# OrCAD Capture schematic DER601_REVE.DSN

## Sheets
1 PAGE1: size C
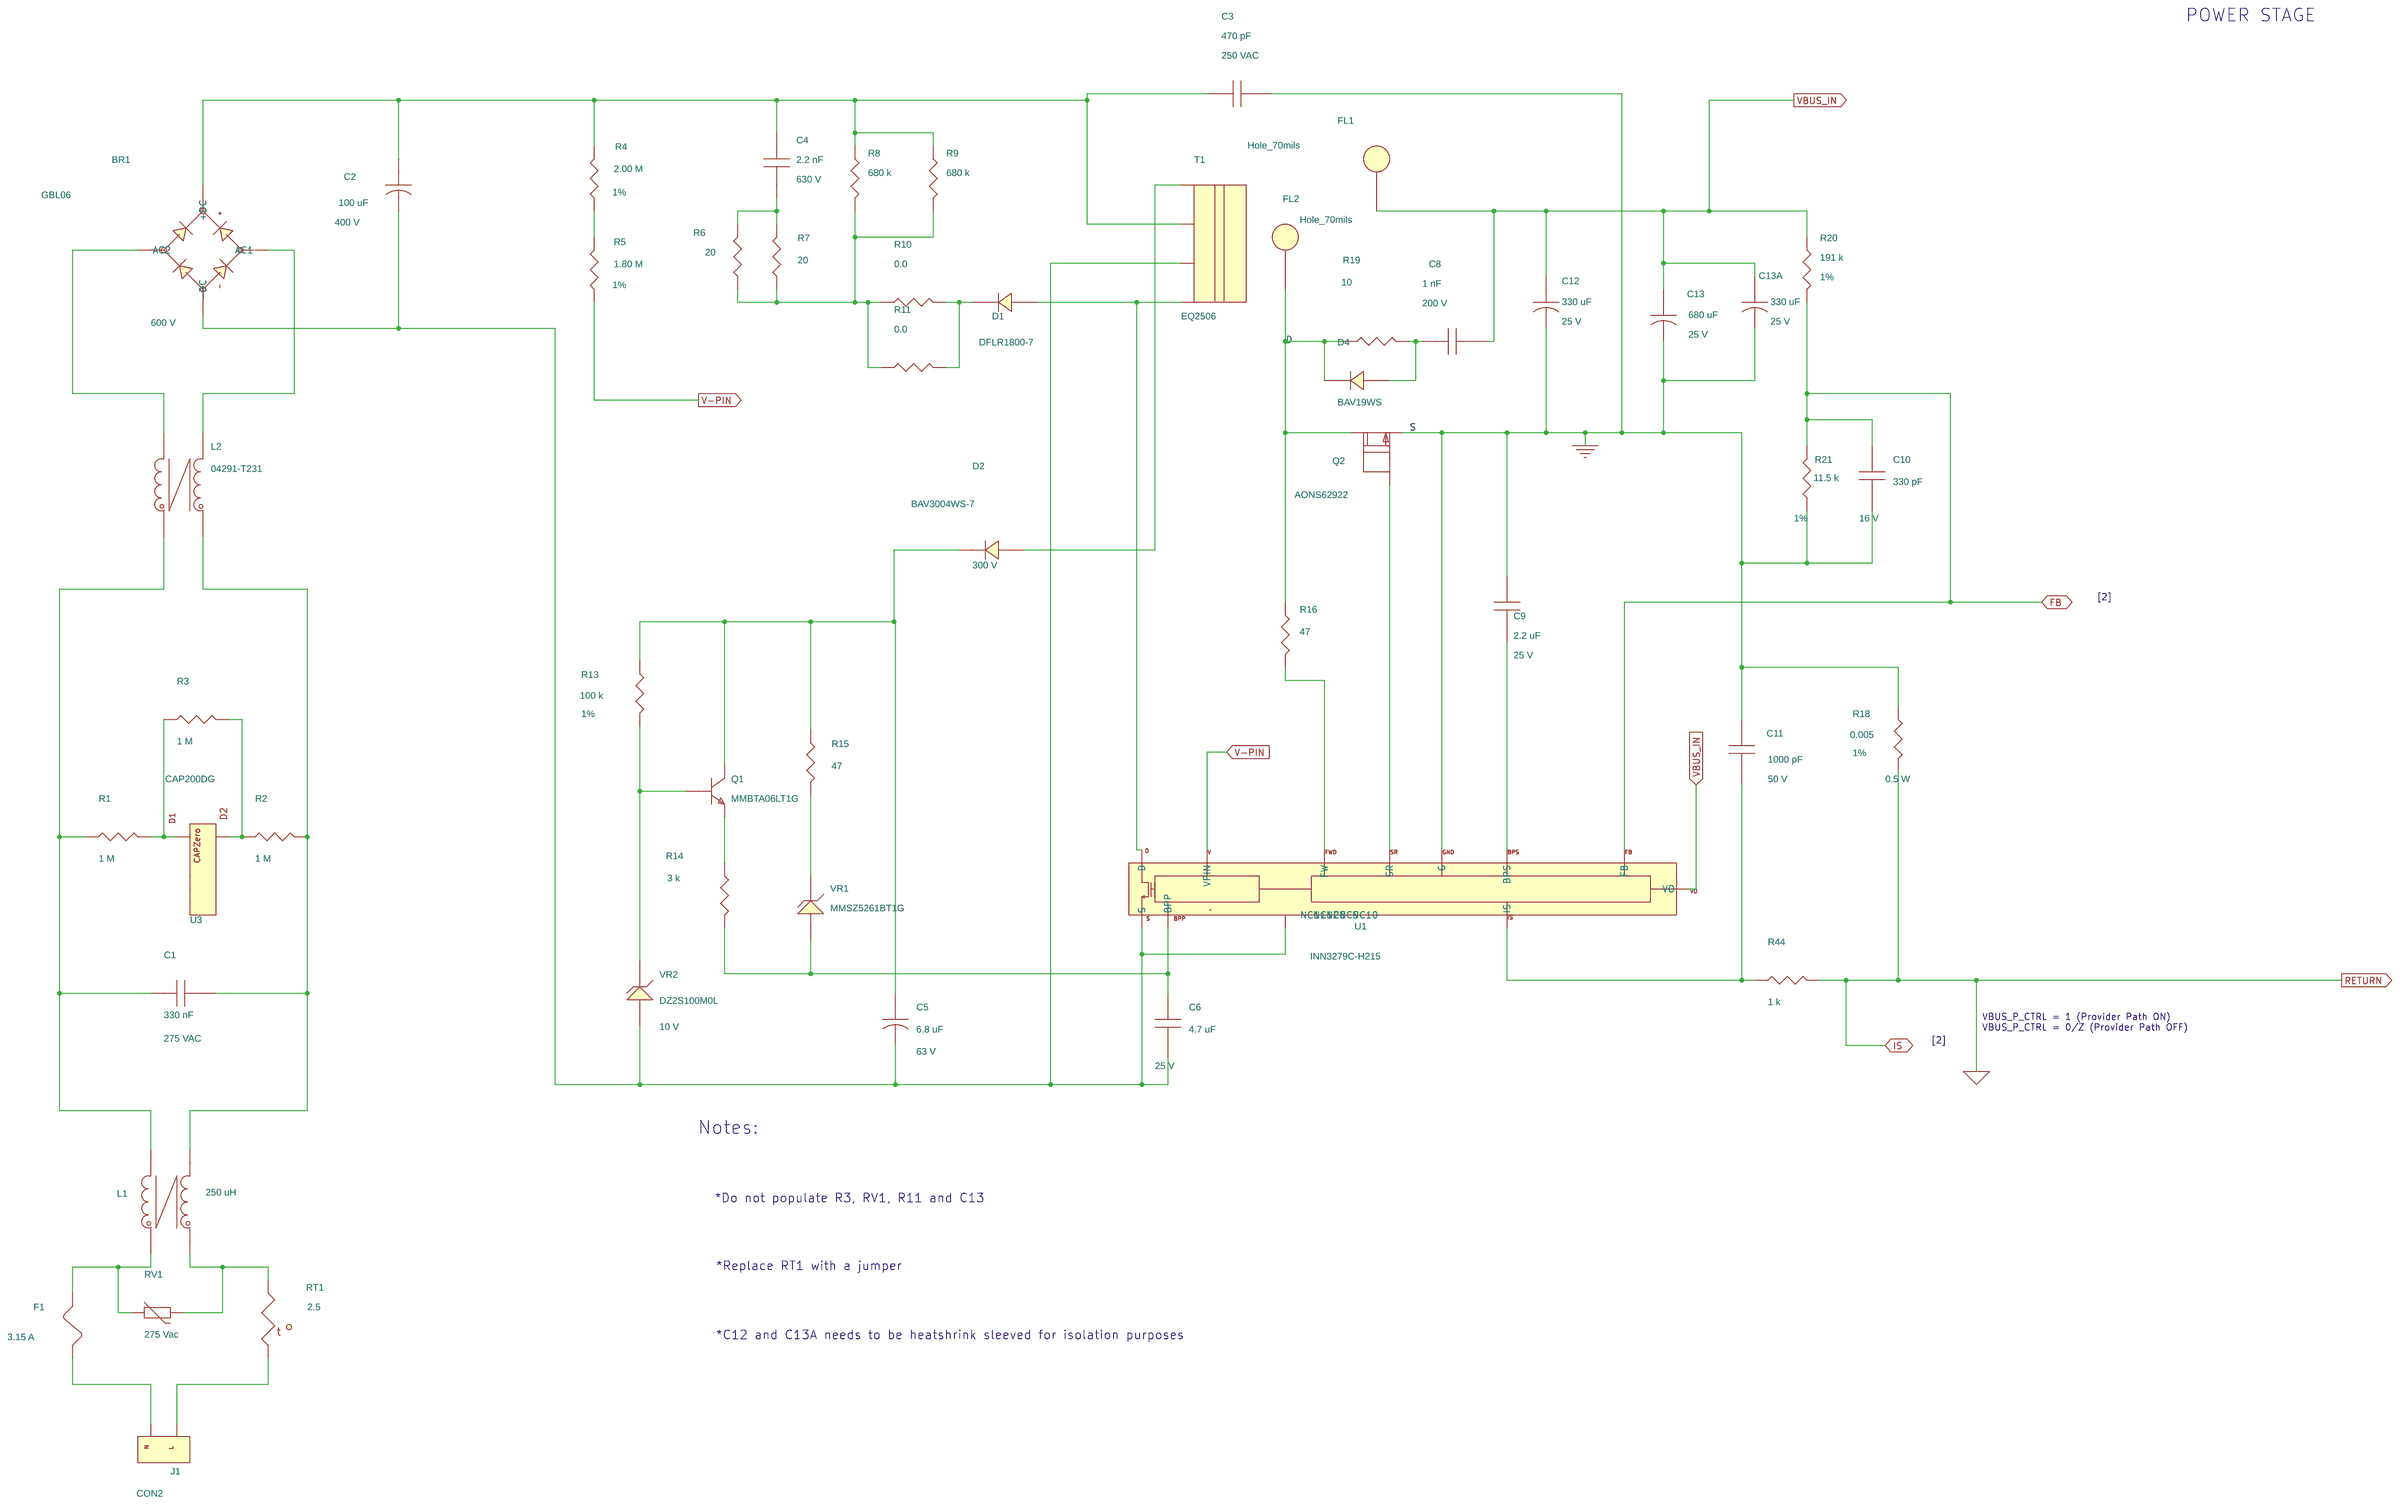
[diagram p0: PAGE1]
2 PAGE2: size Custom
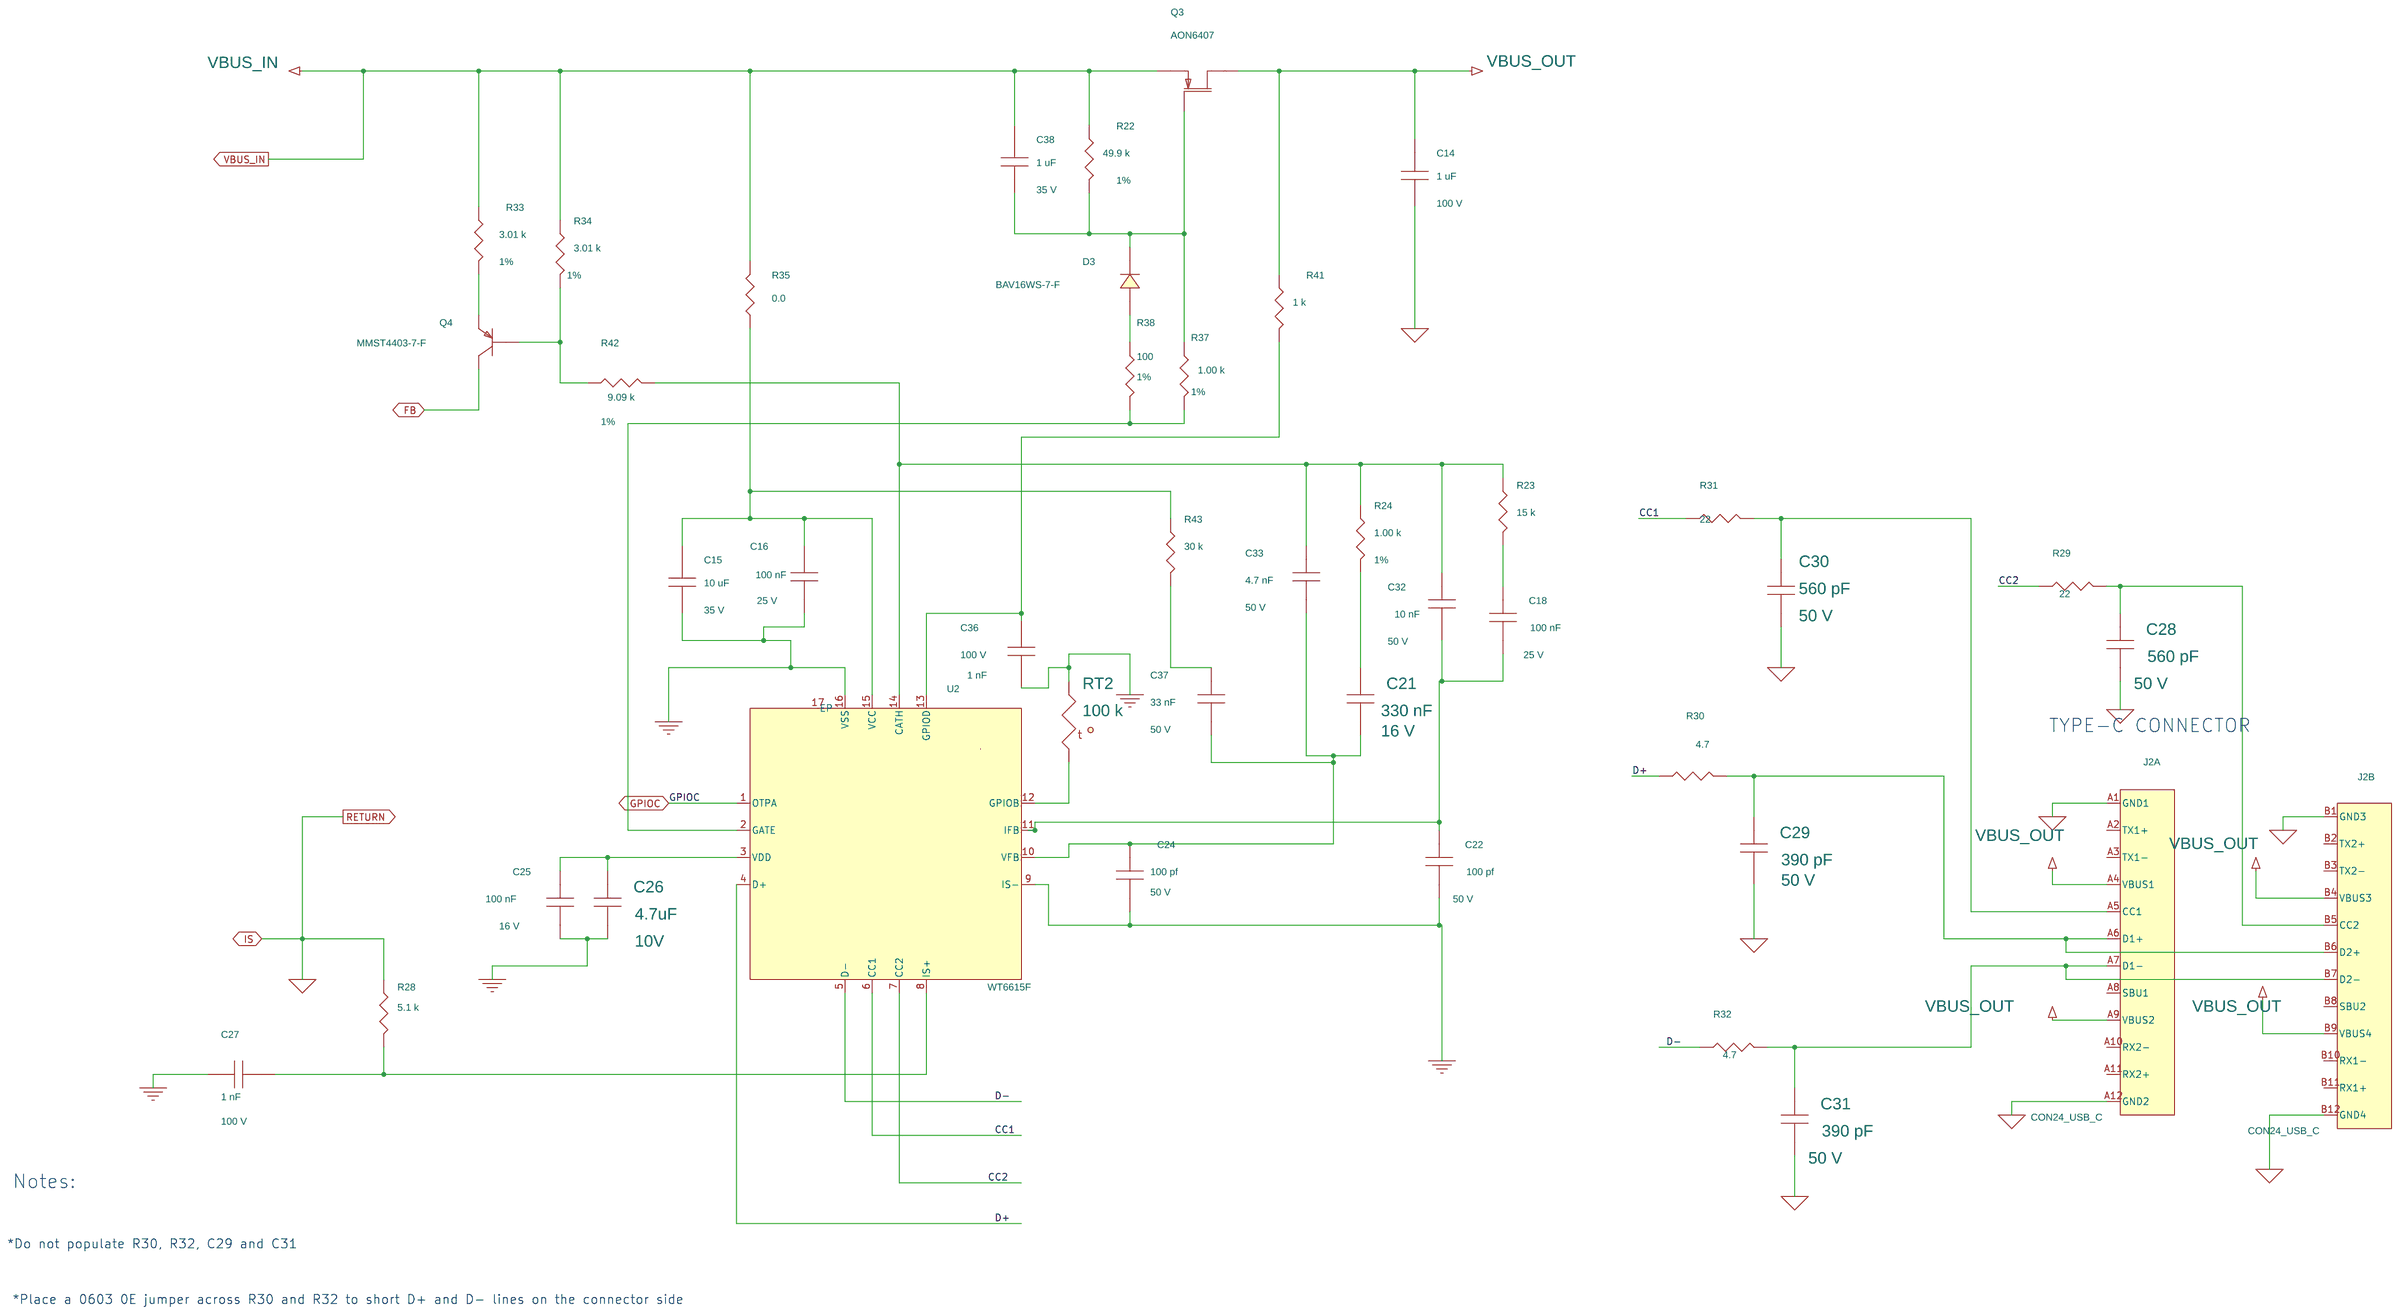
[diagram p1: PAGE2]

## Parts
sheet PAGE1
BR1  GBL06  [pidaxbridgegbl06]
C1  330 nF  [pinp_xcaprad15x8p5x14Hd040]
C2  100 uF  [pipolcapclyd630ls300040]
C3  470 pF  [pinpcaprad374x275ls394d030]
C4  2.2 nF  [pismc1206]
C5  6.8 uF  [pipolcap4p0x11p0xls1p5d030]
C6  4.7 uF  [pismc0805]
C8  1 nF  [pismc0805]
C9  2.2 uF  [pismc0805]
C10  330 pF  [pismr0402]
C11  1000 pF  [pismr0402]
C12  330 uF  [pipolcapcyld315ls138d030]
C13  680 uF  [pipolcapclyd400ls200030]
C13A  330 uF  [pipolcapcyld315ls138d030]
D1  DFLR1800-7  [pismddflr120012]
D2  BAV3004WS-7  [pismsod323]
D4  BAV19WS  [pismsod323]
F1  3.15 A  [pi_rst_microfuse]
FL1  Hole_70mils  [pi_hole_70mil]
FL2  Hole_70mils  [pi_hole_70mil]
J1  CON2  [PI_IEC320-C8]
L1  250 uH  [pi_toroid_CMC4p_V_275uH]
L2  04291-T231  [pi_CMC_18mH_Sumida]
Q1  MMBTA06LT1G  [pismsot23123_1]
Q2  AONS62922  [pismpqfn5x6b]
R1  1 M  [pismr1206]
R2  1 M  [pismr1206]
R3  1 M  [pismr1206]
R4  2.00 M  [pismr1206]
R5  1.80 M  [pismr1206]
R6  20  [pismr1206]
R7  20  [pismr1206]
R8  680 k  [pismr1206]
R9  680 k  [pismr1206]
R10  0.0  [pismr1206]
R11  0.0  [pismr1206]
R13  100 k  [pismr0603]
R14  3 k  [pismr0603]
R15  47  [pismr0603]
R16  47  [pismr0603]
R18  0.005  [pismr0805]
R19  10  [pismr1206]
R20  191 k  [pismr0603]
R21  11.5 k  [pismr0402]
R44  1 k  [pismr0402]
RT1  2.5  [pi_rad150x300ls200d030]
RV1  275 Vac  [pidisc350x160ls210x140040]
T1  EQ2506  [pi_bobbin_eq-2506_4p]
U1  INN3279C-H215  [pi_ic_insop_24d]
U3  CAP200DG  [pi_ic_smd_so8_capzero]
VR1  MMSZ5261BT1G  [pi_sm_sod-123_12]
VR2  DZ2S100M0L  [pi_sm_d_ssmini2p]
sheet PAGE2
C14  1 uF  [pismc1206]
C15  10 uF  [pismc0805]
C16  100 nF  [pismr0402]
C18  100 nF  [pismr0402]
C21  330 nF  [pismc0603]
C22  100 pf  [pismc0402]
C24  100 pf  [pismc0402]
C25  100 nF  [pismr0402]
C26  4.7uF  [pismc0603]
C27  1 nF  [pismr0402]
C28  560 pF  [pismc0603]
C29  390 pF  [pismc0603]
C30  560 pF  [pismc0603]
C31  390 pF  [pismc0603]
C32  10 nF  [pismr0402]
C33  4.7 nF  [pismc0603]
C36  1 nF  [pismr0402]
C37  33 nF  [pismc0603]
C38  1 uF  [pismc0603]
D3  BAV16WS-7-F  [pismsod323]
J2  CON24_USB_C  [pi_conn_USBC_Wurth]  (sections A,B)
Q3  AON6407  [pi_DFN5X6_8L_EP1_P]
Q4  MMST4403-7-F  [pismsot323132]
R22  49.9 k  [pismr0402]
R23  15 k  [pismr0402]
R24  1.00 k  [pismr0402]
R28  5.1 k  [pismr0402]
R29  22  [pismr0402]
R30  4.7  [pismr0402]
R31  22  [pismr0402]
R32  4.7  [pismr0402]
R33  3.01 k  [pismr0402]
R34  3.01 k  [pismr0402]
R35  0.0  [pismr0402]
R37  1.00 k  [pismr0402]
R38  100  [pismr0402]
R41  1 k  [pismr0402]
R42  9.09 k  [pismr0402]
R43  30 k  [pismr0402]
RT2  100 k  [pismr0603]
U2  WT6615F  [pi_sm_16_QFN]

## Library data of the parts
BR1 = DISCRETE_BRIDGE_+~~-: Disp_Voltage: 600 V; Part Number: 15-01112-00
C1 = CAP_NP: ALT_SYMBOLS: pinp_xcaprad15x8p5x14Hd040H; Disp_Voltage: 275 VAC; FPLIST: pinp_xcaprad15x8p5x14Hd040,pinp_xcaprad15x8p5x14Hd040H; Part Number: 20-09095-00; Voltage: 275 VAC
C2 = CAP_POL: ALT_SYMBOLS: pipolcapclyd630ls3000401120h; COMPGROUP: 1; Disp_Voltage: 400 V; FPLIST: pipolcapclyd630ls300040,pipolcapclyd630ls3000401120h; Part Number: 20-00517-00; Voltage: 400 V
C3 = CAP_NP: COMPGROUP: 3; Disp_Voltage: 250 VAC; PCB Editor PCBFP: pinpycaprad540x290ls400040; Part Number: 20-09075-00; Voltage: 250 VAC
C4 = CAP_NP_0: Disp_Voltage: 630 V; Part Number: 20-08609-00; Voltage: 630 V
C5 = CAP_POL: ALT_SYMBOLS: pipolcap4p0x11p0xls1p5d030h; Disp_Voltage: 63 V; FPLIST: pipolcap4p0x11p0xls1p5d030,pipolcap4p0x11p0xls1p5d030h; Part Number: 20-09108-00; Voltage: 63 V
C6 = CAP_NP: Disp_Voltage: 25 V; Part Number: 20-09137-00; Voltage: 16 V
C8 = CAP_NP: ALT_SYMBOLS: pismc0805_1; Disp_Voltage: 200 V; FPLIST: pismc0805,pismc0805_1; PCB Editor PCBFP: pismc0603; Part Number: 20-00737-00; Voltage: 200 V
C9 = CAP_NP_0: Disp_Voltage: 25 V; Part Number: 20-08603-00; Voltage: 25 V
C10 = CAP_NP: ALT_SYMBOLS: pismr0402_1; Disp_Voltage: 16 V; FPLIST: pismr0402,pismr0402_1; Part Number: 20-08910-00; Voltage: 16 V
C11 = CAP_NP: ALT_SYMBOLS: pismr0402_1; Disp_Voltage: 50 V; FPLIST: pismr0402,pismr0402_1; Part Number: 20-09106-00; Voltage: 50 V
C12 C13A = CAP_POL: ALT_SYMBOLS: pipolcapcyld315ls138d030h; Disp_Voltage: 25 V; FPLIST: pipolcapcyld315ls138d030,pipolcapcyld315ls138d030h; Part Number: 20-09107-00; Voltage: 25 V
C13 = CAP_POL: ALT_SYMBOLS: pipolcapclyd400x530ls200030h; Disp_Voltage: 25 V; FPLIST: pipolcapclyd400ls200030,pipolcapclyd400x530ls200030h; Part Number: 20-09047-00; Voltage: 25 V
D1 = DIODE: COMPGROUP: 2; Part Number: 15-00919-00
D2 = DIODE: COMPGROUP: 1; Disp_Voltage: 300 V; Part Number: 15-01138-00
D4 = DIODE: Part Number: 15-00658-00
F1 = FUSE: ALT_SYMBOLS: pirstmicrofusehoz; COMPGROUP: 1; FPLIST: pi_rst_microfuse,pirstmicrofusehoz; Part Number: 40-00020-00
FL1 FL2 = FlyingLead: Part Number: 35-00282-00
J1 = CON2_ACIN: Part Number: 35-00360-00
L1 = TORRID_4P_12_34: ALT_SYMBOLS: pi_toroid_CMC4p_V,pi_toroid_CMC4p_V_275uH; FPLIST: pi_toroid_CMC4p_H,pi_toroid_CMC4p_V,pi_toroid_CMC4p_V_275uH; Part Number: 32-00347-00
L2 = TORRID_4P_12_43a: Part Number: 30-00462-00
Q1 = NPN_BEC: Part Number: 55-00072-00
Q2 = FET_N_SGD_123_4_5678: Part Number: 50-00275-00
R1-R3 = R: Part Number: 05-01424-00
R4 = R: Disp_Tol: 1%; Part Number: 05-03156-00
R5 = R: Disp_Tol: 1%; Part Number: 05-03155-00
R6 R7 = R: Part Number: 05-01311-00
R8 R9 = R: Part Number: 05-01420-00
R10 R11 = R: Part Number: 05-03160-00
R13 = R: Disp_Tol: 1%; Part Number: 05-01174-00
R14 = R: Part Number: 05-01699-00
R15 R16 = R: Part Number: 05-01656-00
R18 = R: Disp_Power: 0.5 W; Disp_Tol: 1%; Part Number: 05-06481-00
R19 = R: Part Number: 05-01304-00
R20 = R: Disp_Tol: 1%; Part Number: 05-01201-00
R21 = R: Disp_Tol: 1%; Part Number: 05-05941-00
R41 R44 = R: ALT_SYMBOLS: pismr0402_1; FPLIST: pismr0402,pismr0402_1; Part Number: 05-03420-00
RT1 = THERMISTOR: ALT_SYMBOLS: pirad400x300ls200040_h; FPLIST: pi_rad150x300ls200d030,pirad400x300ls200040_h; Part Number: 90-00040-00
RV1 = VARISTOR: ALT_SYMBOLS: pi_disc_354x220_ls220x10_040_h; FPLIST: pidisc350x160ls210x140040,pi_disc_354x220_ls220x10_040_h; Part Number: 85-00015-00
T1 = BEQ2506_4P: Part Number: 25-01095-99
U1 = Inno3CP_0: Part Number: 10-01044-07
U3 = CAPZero: Part Number: 10-00958-00
VR1 = DIODE_ZENER: Part Number: 15-01102-00
VR2 = DIODE_ZENER: Disp_Voltage: 10 V; Part Number: 15-00926-00
C14 = CAP_NP: Disp_Voltage: 100 V; Part Number: 20-00993-00; Voltage: 100 V
C15 = CAP_NP: ALT_SYMBOLS: pismc0805_1; Disp_Voltage: 35 V; FPLIST: pismc0805,pismc0805_1; Part Number: 20-08720-00; Voltage: 35 V
C16 C18 = CAP_NP: Disp_Voltage: 25 V; Part Number: 20-08890-00; Voltage: 25 V
C21 = CAP_NP: Disp_Voltage: 16 V; Part Number: 20-08755-00; Voltage: 16 V
C22 C24 = CAP_NP: Disp_Voltage: 50 V; Part Number: 20-09028-00; Voltage: 50 V
C25 = CAP_NP: ALT_SYMBOLS: pismr0402_1; Disp_Voltage: 16 V; FPLIST: pismr0402,pismr0402_1; Part Number: 20-08759-00; Voltage: 16 V
C26 = CAP_NP: Disp_Voltage: 10V; Part Number: 20-08591-00; Voltage: 10 V
C27 C36 = CAP_NP: ALT_SYMBOLS: pismr0402_1; Disp_Voltage: 100 V; FPLIST: pismr0402,pismr0402_1; Part Number: 20-00843-00; Voltage: 100 V
C28-C31 = CAP_NP: Disp_Voltage: 50 V; Part Number: 20-08982-00; Voltage: 50 V
C32 = CAP_NP: Disp_Voltage: 50 V; Part Number: 20-09250-00; Voltage: 50 V
C33 = CAP_NP: Disp_Voltage: 50 V; Part Number: 20-09249-00; Voltage: 50 V
C37 = CAP_NP: Disp_Voltage: 50 V; Part Number: 20-09248-00; Voltage: 50 V
C38 = CAP_NP: ALT_SYMBOLS: pismc0603_1; Disp_Voltage: 35 V; FPLIST: pismc0603,pismc0603_1; Part Number: 20-01134-00; Voltage: 35 V
D3 = DIODE: Part Number: 15-00850-00
J2 = CON24_USB: Part Number: 35-00413-00
Q3 = FET_P_SSSGDDDD: Part Number: 50-00268-00
Q4 = PNP_BEC: Part Number: 55-00064-00
R22 = R: Disp_Tol: 1%; Part Number: 05-06006-00
R23 = R: Part Number: 05-06239-00
R24 R37 = R: ALT_SYMBOLS: pismr0402_1; Disp_Tol: 1%; FPLIST: pismr0402,pismr0402_1; Part Number: 05-05823-00
R28 = R: Part Number: 05-03423-00
R29 R31 = R: Part Number: 05-06177-00
R30 R32 = R: Part Number: 05-06164-00
R33 R34 = R: Disp_Tol: 1%; Part Number: 05-05876-00
R35 = R: Part Number: 05-06420-00
R38 = R: Disp_Tol: 1%; Part Number: 05-05709-00
R42 = R: Disp_Tol: 1%; Part Number: 05-05930-00
R43 = R: Part Number: 05-06246-00
RT2 = THERMISTOR: Part Number: 90-00063-00
U2 = WT6615F: Part Number: 45-00445-00

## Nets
GND: C3.2 C9.1 C10.2 C11.1 C12.2 C13.2 C13A.2 C15.1 C16.2 C22.2 C24.2 C25.2 C26.2 C27.1 C36.2 Q2.1(S) Q2.2(S) Q2.3(S) R18.1 R21.1 RT2.1 U1.2(G) U2.9(IS-) U2.16(VSS)
GND_SIGNAL: C14.1 C28.2 C29.2 C30.2 C31.2 J2.A1(GND1) J2.A12(GND2) J2.B1(GND3) J2.B12(GND4) R18.2 R28.1 R44.2
VBUS_IN: C8.2 C12.1 C13.1 C13A.1 C38.2 FL1.1 Q3.1(S1) R20.1 R22.1 R33.1 R34.1 R35.2 U1.6(VO)
VBUS_OUT: C14.2 J2.A4(VBUS1) J2.A9(VBUS2) J2.B4(VBUS3) J2.B9(VBUS4) Q3.7(D7) R41.1
CC1: R31.1 U2.6(CC1)
CC2: R29.1 U2.7(CC2)
D: D4.1 FL2.1 Q2.5(D) Q2.6(D) Q2.7(D) Q2.8(D) R16.1 R19.2
D+: R30.1 U2.4(D+)
D-: R32.1 U2.5(D-)
EP: U2.17(EP)
FB: C10.1 Q4.3(COLLECTOR) R20.2 R21.2 U1.3(FB)
GPIOC: U2.1(OTPA)
NC8: U1.8(NC8)
NC9: U1.9(NC9)
NC10: U1.10(NC10)
NC11: U1.11(NC11)
NC12: U1.12(NC12)
V-PIN: R5.1 U1.13(VPIN)
N10479111: F1.1 J1.1
N10805923: BR1.4(-DC) C2.2 C5.2 C6.2 T1.3 U1.15 U1.16(S) VR2.2
N10806149: C6.1 R14.2 U1.14(BPP) VR1.2
N10808843: C11.2 R44.1 U1.1(IS)
N10809540: Q2.4(G) U1.5(SR)
N10813018: R4.1 R5.2
N10840366: BR1.1(+DC) C2.1 C3.1 C4.1 R4.2 R8.1 R9.1 T1.2
N10873526: R16.2 U1.7(FW)
N10950053: C5.1 D2.1 Q1.3(COLLECTOR) R13.1 R15.1
N10950141: Q1.2(EMITTER) R14.1
N10950189: Q1.1(BASE) R13.2 VR2.1
N10966650: D1.2 T1.4 U1.24(D)
N11036082: D1.1 R10.2 R11.2
N11077448: R15.2 VR1.1
N11090626: J1.2 RT1.2
N11099981: C1.1 L1.4 L2.4 R1.1
N11100013: C1.2 L1.2 L2.1 R2.2
N11100021: BR1.3(AC2) L2.3
N11100037: BR1.2(AC1) L2.2
N11100069: R1.2 R3.1 U3.2(D1)
N11105883: D2.2 T1.1
N11108210: F1.2 L1.3 RV1.1
N11139529: R6.1 R7.1 R8.2 R9.2 R10.1 R11.1
N11139619: C4.2 R6.2 R7.2
N11156493: C8.1 D4.2 R19.1
N11376604: L1.1 RT1.1 RV1.2
N11381167: R2.1 R3.2 U3.7(D2)
N11415728: C30.1 J2.A5(CC1) R31.2
N11415816: C28.1 J2.B5(CC2) R29.2
N11415954: C29.1 J2.A6(D1+) J2.B6(D2+) R30.2
N11416192: C31.1 J2.A7(D1-) J2.B7(D2-) R32.2
N11423294: C38.1 D3.1 Q3.4(G) R22.2 R37.1
N11423410: Q4.2(EMITTER) R33.2
N11423430: Q4.1(BASE) R34.2 R42.1
N11423458: D3.2 R38.1
N11423484: C15.2 C16.1 R35.1 R43.1 U2.15(VCC)
N11423496: C36.1 R41.2 U2.13(GPIOD)
N11423580: C32.1 C33.1 R23.1 R24.1 R42.2 U2.14(CATH)
N11423600: R37.2 R38.2 U2.2(GATE)
N11423912: C18.1 R23.2
N11423988: C21.2 C24.1 C33.2 C37.2 U2.10(VFB)
N11423992: C21.1 R24.2
N11423996: C18.2 C22.1 C32.2 U2.11(IFB)
N11424272: RT2.2 U2.12(GPIOB)
N11424378: C25.1 C26.1 U2.3(VDD)
N11424618: C27.2 R28.2 U2.8(IS+)
N11433671: C37.1 R43.2
N11471925: C9.2 U1.4(BPS)

Not connected (* = marked no-connect by the designer): J2 A2(TX1+) A3(TX1-) A8(SBU1) A10(RX2-) A11(RX2+) B2(TX2+) B3(TX2-) B8(SBU2) B10(RX1-) B11(RX1+); U3 1(NC1) 3(NC2) 4(NC3) 5(NC4) 6(NC5) 8(NC8)

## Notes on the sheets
sheet 1
- POWER STAGE
- [2]
- VBUS_P_CTRL = 1 (Provider Path ON)
  VBUS_P_CTRL = 0/Z (Provider Path OFF)
- [2]
- Notes:
- *Do not populate R3, RV1, R11 and C13
- *Replace RT1 with a jumper
- *C12 and C13A needs to be heatshrink sleeved for isolation purposes
sheet 2
- TYPE-C CONNECTOR
- Notes:
- *Do not populate R30, R32, C29 and C31
- *Place a 0603 0E jumper across R30 and R32 to short D+ and D- lines on the connector side
